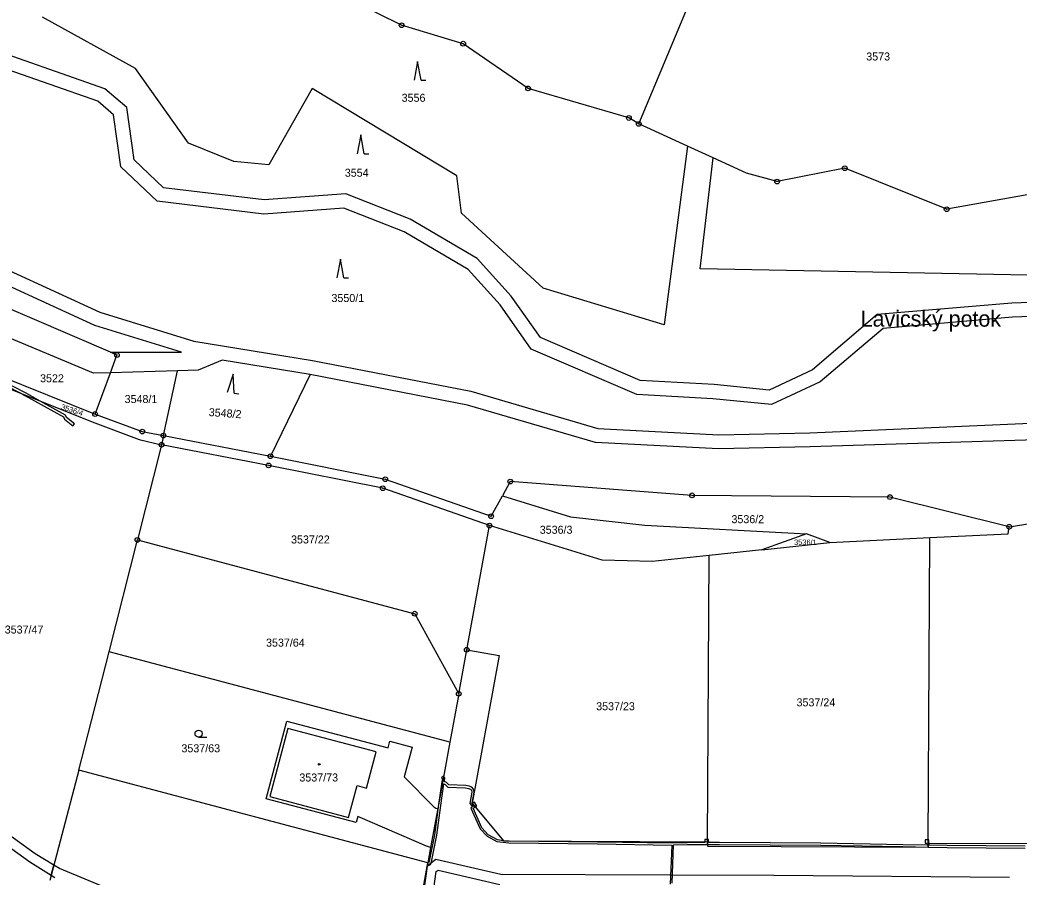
# Model space of a CAD drawing. Extents: x -644096 to -634268, y -1141430 to -1133463.
# Drawn here: x -641189.8 to -640977.5, y -1138235 to -1138053 of the extents above; entities that cross this region are included whole.
import ezdxf

# ---------------------------------------------------------------- set-up
doc = ezdxf.new("R2010")
doc.units = 0
for name, color, linetype in [('_CIVIL_CONSTRUCTION', 7, 'Continuous'), ('B_Hranice _3D', 7, 'Continuous'), ('M_Svah_Nasyp', 7, 'Continuous'), ('M_Svah_Zarez', 7, 'Continuous'), ('svrsek_osa_sjezdy', 7, 'Continuous'), ('svrsek_osa_VRT', 7, 'Continuous'), ('svrsek_popisy_VRT', 7, 'Continuous'), ('terminal_VRT', 7, 'Continuous')]:
    doc.layers.add(name, color=color, linetype=linetype)

msp = doc.modelspace()

# ---------------------------------------------------------------- linework, layer by layer
at = {"layer": '_CIVIL_CONSTRUCTION'}
for centre, radius in [((-641108.66, -1138054.12), 0.5), ((-641108.66, -1138054.12), 0.0303), ((-641095.59, -1138058.02), 0.5), ((-641095.59, -1138058.02), 0.0303), ((-641081.81, -1138067.51), 0.5), ((-641081.81, -1138067.51), 0.0303), ((-641060.39, -1138073.8), 0.5), ((-641060.39, -1138073.8), 0.0303), ((-641058.28, -1138075.06), 0.5), ((-641058.28, -1138075.06), 0.0303), ((-641014.51, -1138084.47), 0.5), ((-641014.51, -1138084.47), 0.0303), ((-641028.88, -1138087.32), 0.5), ((-641028.88, -1138087.32), 0.0303), ((-640992.86, -1138093.18), 0.5), ((-640992.86, -1138093.18), 0.0303), ((-641169.15, -1138124.14), 0.5), ((-641169.15, -1138124.14), 0.0303), ((-641173.78, -1138136.67), 0.5), ((-641173.78, -1138136.67), 0.0303), ((-641163.77, -1138140.39), 0.5), ((-641163.77, -1138140.39), 0.0303), ((-641159.28, -1138141.25), 0.5), ((-641159.28, -1138141.25), 0.0303), ((-641159.66, -1138143.21), 0.5), ((-641159.66, -1138143.21), 0.0303), ((-641136.55, -1138145.63), 0.5), ((-641136.55, -1138145.63), 0.0303), ((-641136.94, -1138147.59), 0.5), ((-641136.94, -1138147.59), 0.0303), ((-641112.14, -1138150.51), 0.5), ((-641112.14, -1138150.51), 0.0303), ((-641085.58, -1138151.03), 0.5), ((-641112.67, -1138152.44), 0.5), ((-641112.67, -1138152.44), 0.0303), ((-641085.58, -1138151.03), 0.0303), ((-641046.98, -1138153.94), 0.5), ((-641046.98, -1138153.94), 0.0303), ((-641004.91, -1138154.32), 0.5), ((-641004.91, -1138154.32), 0.0303), ((-641089.65, -1138158.39), 0.5), ((-641089.65, -1138158.39), 0.0303), ((-641090.01, -1138160.37), 0.5), ((-641090.01, -1138160.37), 0.0303), ((-640979.58, -1138160.62), 0.5), ((-640979.58, -1138160.62), 0.0303), ((-641164.8, -1138163.42), 0.5), ((-641164.8, -1138163.42), 0.0303), ((-641105.89, -1138179.07), 0.5), ((-641105.89, -1138179.07), 0.0303), ((-641094.83, -1138186.72), 0.5), ((-641094.83, -1138186.72), 0.0303), ((-641096.54, -1138196.06), 0.5), ((-641096.54, -1138196.06), 0.0303)]:
    msp.add_circle(centre, radius, dxfattribs=at)
at = {"layer": 'B_Hranice _3D'}
for points in [[(-641196.8, -1138128), (-641196.99, -1138128.46), (-641189.31, -1138132.4), (-641188.7, -1138132.71), (-641180.5, -1138137.26), (-641180.3, -1138137.73), (-641178.52, -1138139.16), (-641178.2, -1138138.78), (-641179.88, -1138137.41), (-641180.1, -1138136.9), (-641185.44, -1138133.95), (-641188.46, -1138132.27)], [(-641216.88, -1138210.78), (-641216.79, -1138210.82), (-641187.67, -1138231.78), (-641183.1, -1138234.61), (-641182.54, -1138232.48), (-641186.51, -1138230.04), (-641215.75, -1138208.97), (-641216.31, -1138208.71), (-641216.41, -1138208.66)], [(-641100.16, -1138213.92), (-641099.99, -1138214.1), (-641100.12, -1138214.81), (-641100.85, -1138219.63), (-641101.65, -1138226.02), (-641102.83, -1138231.63), (-641102.95, -1138232), (-641103.14, -1138232.12), (-641103.24, -1138232.69), (-641102.53, -1138232.36), (-641102.35, -1138231.75), (-641101.15, -1138226.1), (-641100.37, -1138219.83), (-641099.67, -1138215.23), (-641099.43, -1138215.35), (-641098.87, -1138215.92), (-641095.06, -1138216.03), (-641094.44, -1138216.18), (-641094.03, -1138216.33), (-641093.85, -1138216.53), (-641093.77, -1138216.95), (-641094.19, -1138219.35), (-641093.79, -1138219.84), (-641093.09, -1138220), (-641093.67, -1138219.3), (-641093.61, -1138218.96), (-641093.27, -1138216.95), (-641093.39, -1138216.31), (-641093.73, -1138215.91), (-641094.3, -1138215.7), (-641095, -1138215.53), (-641098.65, -1138215.42), (-641099.13, -1138214.93), (-641099.59, -1138214.71), (-641099.45, -1138213.94), (-641099.75, -1138213.62), (-641099.79, -1138213.58)], [(-641043.65, -1138228.08), (-641043.52, -1138228.08), (-641041.16, -1138228.09), (-641019.57, -1138228.24), (-641002.15, -1138228.53), (-640996.82, -1138228.68), (-640996.82, -1138227.78), (-640996.82, -1138227.13), (-640997.45, -1138227.13), (-640997.43, -1138227.81), (-640997.11, -1138227.79), (-640996.96, -1138228.25), (-641002.15, -1138228.13), (-641019.57, -1138227.84), (-641041.16, -1138227.69), (-641043.32, -1138227.68), (-641043.48, -1138227.47), (-641043.5, -1138227.01), (-641043.65, -1138227.01), (-641043.65, -1138227.53)]]:
    msp.add_lwpolyline(points, close=True, dxfattribs=at)
for points in [[(-641051.19, -1138236.27), (-641050.89, -1138228.19), (-641047.92, -1138228.11), (-641043.65, -1138228.08), (-641043.65, -1138227.53), (-641043.65, -1138227.01), (-641044.25, -1138227), (-641044.26, -1138227.64), (-641047.92, -1138227.71), (-641051.08, -1138227.8), (-641067.08, -1138227.57), (-641085.85, -1138227.36), (-641087.04, -1138227.29), (-641088.3, -1138227.08), (-641090.25, -1138226.02), (-641091.65, -1138224.56), (-641093.48, -1138220.4), (-641092.7, -1138219.98), (-641093.17, -1138219.07), (-641093.75, -1138219.38), (-641093.53, -1138219.76), (-641093.94, -1138220.36), (-641091.99, -1138224.78), (-641090.49, -1138226.34), (-641088.42, -1138227.46), (-641085.87, -1138227.76), (-641067.08, -1138227.97), (-641051.28, -1138228.2), (-641051.62, -1138236.49)], [(-640976.2, -1138228.47), (-640992.74, -1138228.33), (-640996.6, -1138228.25), (-640996.64, -1138227.13), (-640996.82, -1138227.13), (-640996.82, -1138227.78), (-640996.82, -1138228.68), (-640992.74, -1138228.73), (-640976.2, -1138228.87)], [(-640979.51, -1138235.1), (-641029.59, -1138234.66), (-641051.65, -1138234.58), (-641087.57, -1138234.45), (-641101.39, -1138231.31), (-641103.24, -1138232.67), (-641105.64, -1138250.05)], [(-641156.96, -1138243.33), (-641181.36, -1138233.21), (-641182.54, -1138232.48), (-641183.1, -1138234.61), (-641182.32, -1138235.09)], [(-641103.57, -1138250.41), (-641101.3, -1138233.85), (-641100.92, -1138233.57), (-641087.83, -1138236.59)]]:
    msp.add_lwpolyline(points, dxfattribs=at)
at = {"layer": 'M_Svah_Nasyp'}
for p, q in [((-641132.81, -1138203.45), (-641136.65, -1138217.91)), ((-641114.05, -1138208.44), (-641132.81, -1138203.45)), ((-641116.1, -1138216.12), (-641114.05, -1138208.44)), ((-641119.92, -1138222.34), (-641118.11, -1138215.58)), ((-641118.11, -1138215.58), (-641116.1, -1138216.12)), ((-641136.65, -1138217.91), (-641119.92, -1138222.34))]:
    msp.add_line(p, q, dxfattribs=at)
at = {"layer": 'M_Svah_Zarez'}
msp.add_circle((-641126.17, -1138211.08), 0.175, dxfattribs=at)
at = {"layer": 'svrsek_osa_sjezdy'}
for p, q in [((-641105.28, -1138061.78), (-641106.03, -1138065.78)), ((-641104.53, -1138065.78), (-641105.28, -1138061.78)), ((-641104.53, -1138065.78), (-641103.53, -1138065.78)), ((-641117.36, -1138077.39), (-641118.11, -1138081.39)), ((-641116.61, -1138081.39), (-641117.36, -1138077.39)), ((-641116.61, -1138081.39), (-641115.61, -1138081.39)), ((-641121.67, -1138103.75), (-641122.42, -1138107.75)), ((-641120.92, -1138107.75), (-641121.67, -1138103.75)), ((-641120.92, -1138107.75), (-641119.92, -1138107.75)), ((-641144.47, -1138128.21), (-641145.7, -1138132.09)), ((-641144.22, -1138132.27), (-641144.47, -1138128.21)), ((-641144.22, -1138132.27), (-641143.23, -1138132.39)), ((-641151.81, -1138205.3), (-641150.06, -1138205.3))]:
    msp.add_line(p, q, dxfattribs=at)
msp.add_circle((-641151.81, -1138204.55), 0.75, dxfattribs=at)
at = {"layer": 'terminal_VRT'}
for p, q in [((-641047.95, -1138079.77), (-641058.28, -1138075.06)), ((-641042.49, -1138082.26), (-641047.95, -1138079.77)), ((-641196.61, -1138127.54), (-641173.78, -1138136.67)), ((-641156.27, -1138127.5), (-641170.54, -1138127.89)), ((-641159.28, -1138141.25), (-641156.27, -1138127.5)), ((-641151.92, -1138127.38), (-641156.27, -1138127.5)), ((-641173.78, -1138136.67), (-641170.54, -1138127.89)), ((-641128.11, -1138128.28), (-641136.55, -1138145.63)), ((-641159.28, -1138141.25), (-641159.66, -1138143.21)), ((-641159.28, -1138141.25), (-641136.55, -1138145.63)), ((-641159.66, -1138143.21), (-641164.8, -1138163.42)), ((-641094.83, -1138186.72), (-641090.01, -1138160.37)), ((-641170.83, -1138187.16), (-641164.8, -1138163.42)), ((-641022.64, -1138162.11), (-641032.12, -1138165.54)), ((-641017.69, -1138163.97), (-641022.64, -1138162.11)), ((-641017.69, -1138163.97), (-640996.47, -1138162.92)), ((-640996.82, -1138227.78), (-640996.47, -1138162.92)), ((-641032.12, -1138165.54), (-641043.32, -1138166.73)), ((-641032.12, -1138165.54), (-641017.69, -1138163.97)), ((-641043.65, -1138227.53), (-641043.32, -1138166.73)), ((-641096.54, -1138196.06), (-641094.83, -1138186.72)), ((-641098.43, -1138206.39), (-641170.83, -1138187.16)), ((-641096.54, -1138196.06), (-641098.43, -1138206.39)), ((-641098.43, -1138206.39), (-641101, -1138220.46)), ((-641177.25, -1138212.28), (-641183.39, -1138235.71)), ((-641103.11, -1138231.97), (-641177.25, -1138212.28)), ((-641101, -1138220.46), (-641102.52, -1138228.75)), ((-641102.52, -1138228.75), (-641103.11, -1138231.97)), ((-640996.82, -1138227.78), (-640953.15, -1138228.02)), ((-641105.4, -1138244.5), (-641103.11, -1138231.97))]:
    msp.add_line(p, q, dxfattribs=at)
for points in [[(-641058.28, -1138075.06), (-641045.97, -1138045.52), (-641040.86, -1138011.38)], [(-641058.28, -1138075.06), (-641060.39, -1138073.8), (-641081.81, -1138067.51), (-641095.59, -1138058.02), (-641108.66, -1138054.12), (-641118.63, -1138049.22), (-641144.85, -1138041.7), (-641144.82, -1138034.41)], [(-641047.95, -1138079.77), (-641052.87, -1138117.72), (-641078.6, -1138109.94), (-641095.96, -1138094.05), (-641096.94, -1138086.11), (-641127.66, -1138067.51), (-641136.9, -1138083.74), (-641144.31, -1138083.01), (-641153.92, -1138079.14), (-641165.21, -1138063.31), (-641184.96, -1138052.36)], [(-640959.27, -1138112.41), (-640979.05, -1138113.1), (-641007.6, -1138115.57), (-641021.37, -1138127.26), (-641030.59, -1138131.6), (-641042.29, -1138130.42), (-641058.01, -1138129.58), (-641079.18, -1138120.45), (-641085.38, -1138111.62), (-641092.58, -1138103.61), (-641106.84, -1138095.27), (-641120.5, -1138089.93), (-641137.84, -1138091.19), (-641159.25, -1138088.6), (-641165.47, -1138082.7), (-641167.07, -1138071.58), (-641171.72, -1138067.61), (-641199.22, -1138057.99)], [(-640959.23, -1138115.41), (-640978.87, -1138116.1), (-641006.39, -1138118.48), (-641019.73, -1138129.81), (-641030.07, -1138134.67), (-641042.52, -1138133.41), (-641058.71, -1138132.55), (-641081.15, -1138122.87), (-641087.73, -1138113.49), (-641094.5, -1138105.96), (-641108.15, -1138097.98), (-641120.96, -1138092.97), (-641137.91, -1138094.2), (-641160.59, -1138091.46), (-641168.29, -1138084.16), (-641169.88, -1138073.13), (-641173.24, -1138070.26), (-641199.66, -1138061.02)], [(-640818.99, -1138107.63), (-640914.76, -1138103.97), (-640916.81, -1138108.33), (-641045.24, -1138105.85), (-641042.49, -1138082.26)], [(-640967.8, -1138088.73), (-640992.86, -1138093.18), (-641014.51, -1138084.47), (-641028.88, -1138087.32), (-641035.39, -1138085.5), (-641042.49, -1138082.26)], [(-641244.21, -1138086.95), (-641234.4, -1138092.05), (-641201.79, -1138101.76), (-641172.76, -1138115.04), (-641152.82, -1138121.22), (-641127.58, -1138125.33), (-641093.99, -1138131.84), (-641066.97, -1138139.72), (-641041.29, -1138141.09), (-641021.94, -1138140.66), (-640939.51, -1138137.08), (-640892.07, -1138138.59), (-640868.78, -1138141.01), (-640813.5, -1138141.75), (-640793.59, -1138144.46), (-640759.49, -1138152.75), (-640696.46, -1138171.98), (-640684.63, -1138177.83), (-640658.32, -1138185.71), (-640648.46, -1138194.4), (-640615.44, -1138213.12)], [(-641173.83, -1138117.85), (-641202.85, -1138104.58), (-641235.53, -1138094.84), (-641246.82, -1138088.96)], [(-641170.5, -1138123.56), (-641203.88, -1138109.26), (-641215.09, -1138105.84), (-641254.58, -1138099.39), (-641255.25, -1138099.57)], [(-641170.54, -1138127.89), (-641174.13, -1138127.99), (-641196.36, -1138118.7)], [(-641170.5, -1138123.56), (-641155.41, -1138123.56), (-641173.83, -1138117.85)], [(-641170.54, -1138127.89), (-641169.15, -1138124.14), (-641170.5, -1138123.56)], [(-641128.11, -1138128.28), (-641146.78, -1138125.24), (-641151.92, -1138127.38)], [(-641197.3, -1138129.2), (-641174.43, -1138138.35), (-641164.43, -1138142.07), (-641159.66, -1138143.21)], [(-640620.96, -1138214.55), (-640648.48, -1138198.63), (-640660.2, -1138189.32), (-640686.1, -1138181.57), (-640697.94, -1138175.71), (-640760.55, -1138156.61), (-640794.33, -1138148.4), (-640813.8, -1138145.75), (-640869.01, -1138145.01), (-640892.34, -1138142.58), (-640939.51, -1138141.08), (-641021.86, -1138143.66), (-641041.34, -1138144.09), (-641067.48, -1138142.7), (-641094.7, -1138134.76), (-641128.11, -1138128.28)], [(-641173.78, -1138136.67), (-641163.77, -1138140.39), (-641159.28, -1138141.25)], [(-641090.01, -1138160.37), (-641112.67, -1138152.44), (-641136.94, -1138147.59), (-641159.66, -1138143.21)], [(-641136.55, -1138145.63), (-641112.14, -1138150.51), (-641089.65, -1138158.39), (-641087.23, -1138154.01)], [(-640979.58, -1138160.62), (-641004.91, -1138154.32), (-641046.98, -1138153.94), (-641085.58, -1138151.03), (-641087.23, -1138154.01)], [(-641087.23, -1138154.01), (-641072.81, -1138158.52), (-641057.01, -1138160.28), (-641022.64, -1138162.11)], [(-640979.58, -1138160.62), (-640961.31, -1138157.7), (-640952.76, -1138157.14)], [(-641043.32, -1138166.73), (-641055.44, -1138168.02), (-641066.03, -1138167.68), (-641090.01, -1138160.37)], [(-640996.47, -1138162.92), (-640979.77, -1138162.1), (-640979.58, -1138160.62)], [(-641164.8, -1138163.42), (-641105.89, -1138179.07), (-641096.54, -1138196.06)], [(-641094.83, -1138186.72), (-641087.95, -1138187.98), (-641093.67, -1138219.3), (-641087.04, -1138227.29), (-641043.65, -1138227.53)], [(-641177.25, -1138212.28), (-641176.04, -1138207.66), (-641170.83, -1138187.16)], [(-641102.52, -1138228.75), (-641103.41, -1138228.47), (-641117.98, -1138222.11), (-641118.33, -1138223.43), (-641137.45, -1138218.38), (-641133.06, -1138201.87), (-641111.55, -1138207.59), (-641111.17, -1138206.14), (-641106.43, -1138207.4), (-641108.14, -1138213.73), (-641101.8, -1138220.08), (-641101.38, -1138220.38), (-641101, -1138220.46)], [(-641043.65, -1138227.53), (-641043.65, -1138228.43), (-640996.82, -1138228.68), (-640996.82, -1138227.78)]]:
    msp.add_lwpolyline(points, dxfattribs=at)

# ---------------------------------------------------------------- texts
at = {"layer": 'svrsek_osa_VRT'}
for s, height, p in [('3573', 1.7, (-641009.95, -1138061.59)), ('3556', 1.7, (-641108.66, -1138070.36)), ('3554', 1.7, (-641120.74, -1138086.28)), ('3550/1', 1.7, (-641123.57, -1138112.88)), ('3522', 1.7, (-641185.48, -1138129.93)), ('3548/1', 1.7, (-641167.52, -1138134.34)), ('3536/2', 1.7, (-641038.59, -1138159.85)), ('3536/3', 1.7, (-641079.32, -1138162.1)), ('3537/22', 1.7, (-641132.16, -1138164.16)), ('3536/1', 1.14, (-641025.28, -1138164.47)), ('3537/47', 1.7, (-641192.99, -1138183.29)), ('3537/64', 1.7, (-641137.47, -1138186.07)), ('3537/24', 1.7, (-641024.76, -1138198.75)), ('3537/23', 1.7, (-641067.33, -1138199.58)), ('3537/63', 1.7, (-641155.45, -1138208.51)), ('3537/73', 1.7, (-641130.39, -1138214.71))]:
    msp.add_text(s, height=height, dxfattribs=at).set_placement(p)
for s, height, rotation, p in [('3536/4', 1.14, 342, (-641181.13, -1138135.62)), ('3548/2', 1.7, 356, (-641149.69, -1138137.1))]:
    msp.add_text(s, height=height, rotation=rotation, dxfattribs=at).set_placement(p)
at = {"layer": 'svrsek_popisy_VRT'}
msp.add_text('Lavicský potok', height=3.4, dxfattribs=at).set_placement((-641011.13, -1138118.12))

doc.saveas('drawing.dxf')
